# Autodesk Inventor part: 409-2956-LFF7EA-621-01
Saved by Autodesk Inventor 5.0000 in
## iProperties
Created: 2010-06
Part Number: 409-2956-LFF7EA-621-01
Cost Center: 0 lbmass
Material: A36 STEEL PLATE
Document SubType Name: Sheet Metal
Designer: S. Boerckel
Authority: 0 in^3
Mass: 8052.98 g
Surface Area: 761.54 cm^2
Volume: 1024.55 cm^3
Density: 7.86 g/cm^3
Flat Pattern Width: 15.24 cm
Flat Pattern Length: 15.24 cm
Flat Pattern Area: 232.258 cm^2
Sheet Metal Rule: 1-3/4" THK
Sheet Metal Width: 10.0000 in
Sheet Metal Length: 50.0000 in^2
Description: STRAINER FOOT PLATE
User Status: BURN
SaveDate: 2008-01-15
SaveTime: 10:24
FileName: Sheet Metal
Wide: =<Flat Pattern Width>cm
Length: =<Flat Pattern Length>cm
Thickness: 1.7500 in
SMR: =<Sheet Metal Rule> - <Material>
Author: S. Boerckel
Revision Number: 0
Subject: DEMIN WATER FORWARDING PUMP SKID-7EA
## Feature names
1. Hole2
2. Plate1
